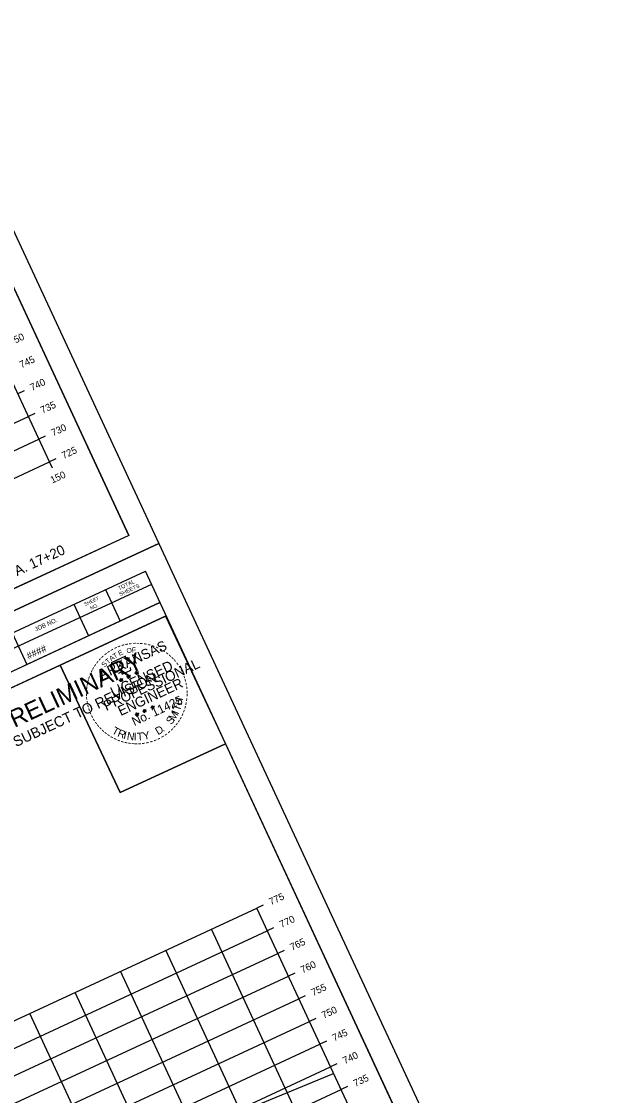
# Model space of a CAD drawing. Extents: x 1354696 to 1366163, y 660729 to 670380.
# Drawn here: x 1358367.5 to 1358484.8, y 665766.1 to 665980.8 of the extents above; entities that cross this region are included whole.
import ezdxf

# ---------------------------------------------------------------- set-up
doc = ezdxf.new("R2010")
doc.units = 0
for name, color, linetype in [('R_Axis', 7, 'Continuous'), ('R_Axis Annot', 7, 'Continuous'), ('R_Border', 7, 'Continuous'), ('R_Border PE', 7, 'Continuous'), ('R_Border Prem', 7, 'Continuous'), ('R_Draft', 7, 'Continuous'), ('R_Exist Surface', 7, 'Continuous'), ('R_Grid', 7, 'Continuous'), ('R_No Plot', 7, 'Continuous')]:
    doc.layers.add(name, color=color, linetype=linetype)

msp = doc.modelspace()

# ---------------------------------------------------------------- linework, layer by layer
at = {"layer": 'R_Axis'}
for p, q in [((1358373.11, 665892.75), (1358352.05, 665938.1)), ((1358368.06, 665906.95), (1358366.79, 665906.36)), ((1358370.17, 665902.41), (1358368.9, 665901.82)), ((1358372.27, 665897.88), (1358371, 665897.29)), ((1358101, 665766.42), (1358373.11, 665892.75)), ((1358374.38, 665893.34), (1358373.11, 665892.75)), ((1358373.7, 665891.48), (1358373.11, 665892.75)), ((1358415.79, 665804.15), (1358414.52, 665803.56)), ((1358435.57, 665758.21), (1358414.52, 665803.56)), ((1358417.89, 665799.61), (1358416.62, 665799.02)), ((1358420, 665795.08), (1358418.73, 665794.49)), ((1358422.1, 665790.54), (1358420.83, 665789.95)), ((1358424.21, 665786.01), (1358422.94, 665785.42)), ((1358426.32, 665781.47), (1358425.05, 665780.88)), ((1358428.42, 665776.94), (1358427.15, 665776.35)), ((1358430.53, 665772.4), (1358429.26, 665771.81)), ((1358432.63, 665767.87), (1358431.36, 665767.28))]:
    msp.add_line(p, q, dxfattribs=at)
at = {"layer": 'R_Border'}
for p, q in [((1358388.95, 665878.06), (1358302.43, 666064.41)), ((1358388.95, 665878.06), (1358102.17, 665744.91)), ((1358105.49, 665737.77), (1358392.27, 665870.91)), ((1358478.79, 665684.56), (1358392.27, 665870.91)), ((1358393.5, 665868.26), (1358393.5, 665868.26)), ((1358393.5, 665868.25), (1358354.41, 665850.1)), ((1358384.28, 665867.21), (1358387.21, 665860.91)), ((1358395.19, 665864.62), (1358356.1, 665846.47)), ((1358358.78, 665847.71), (1358395.19, 665864.62)), ((1358377.99, 665864.28), (1358380.91, 665857.99)), ((1358396.43, 665861.95), (1358339.61, 665835.57)), ((1358365.67, 665858.57), (1358368.6, 665852.27))]:
    msp.add_line(p, q, dxfattribs=at)
at = {"layer": 'R_Border PE'}
for p, q in [((1358387.07, 665849.07), (1358387.32, 665849.13)), ((1358387.07, 665849.07), (1358387.43, 665849.11)), ((1358387.07, 665849.07), (1358387.33, 665849.06)), ((1358387.43, 665849.11), (1358387.28, 665849.44)), ((1358387.28, 665849.44), (1358387.43, 665849.24)), ((1358387.28, 665849.44), (1358387.35, 665849.2)), ((1358387.36, 665848.75), (1358387.43, 665849.11)), ((1358387.36, 665848.75), (1358387.46, 665849.04)), ((1358387.36, 665848.75), (1358387.37, 665849.03)), ((1358387.7, 665849.36), (1358387.43, 665849.11)), ((1358387.75, 665848.93), (1358387.43, 665849.11)), ((1358387.7, 665849.36), (1358387.46, 665849.19)), ((1358387.75, 665848.93), (1358387.46, 665849.04)), ((1358387.75, 665848.93), (1358387.5, 665849.14)), ((1358387.7, 665849.36), (1358387.56, 665849.18)), ((1358388.58, 665849.77), (1358388.83, 665849.84)), ((1358388.58, 665849.77), (1358388.95, 665849.82)), ((1358388.58, 665849.77), (1358388.85, 665849.76)), ((1358388.95, 665849.82), (1358388.79, 665850.15)), ((1358388.79, 665850.15), (1358388.94, 665849.94)), ((1358388.79, 665850.15), (1358388.86, 665849.9)), ((1358388.87, 665849.46), (1358388.95, 665849.82)), ((1358388.87, 665849.46), (1358388.98, 665849.74)), ((1358388.87, 665849.46), (1358388.89, 665849.73)), ((1358389.21, 665850.06), (1358388.95, 665849.82)), ((1358389.26, 665849.64), (1358388.95, 665849.82)), ((1358389.21, 665850.06), (1358388.97, 665849.9)), ((1358389.26, 665849.64), (1358388.98, 665849.74)), ((1358389.26, 665849.64), (1358389.02, 665849.84)), ((1358389.21, 665850.06), (1358389.07, 665849.88)), ((1358390.19, 665850.5), (1358390.44, 665850.57)), ((1358390.19, 665850.5), (1358390.55, 665850.55)), ((1358390.19, 665850.5), (1358390.45, 665850.49)), ((1358390.55, 665850.55), (1358390.4, 665850.88)), ((1358390.4, 665850.88), (1358390.55, 665850.67)), ((1358390.4, 665850.88), (1358390.47, 665850.63)), ((1358390.48, 665850.19), (1358390.55, 665850.55)), ((1358390.48, 665850.19), (1358390.58, 665850.47)), ((1358390.48, 665850.19), (1358390.49, 665850.46)), ((1358390.82, 665850.79), (1358390.55, 665850.55)), ((1358390.87, 665850.37), (1358390.55, 665850.55)), ((1358390.82, 665850.79), (1358390.58, 665850.63)), ((1358390.87, 665850.37), (1358390.58, 665850.47)), ((1358390.87, 665850.37), (1358390.62, 665850.57)), ((1358390.82, 665850.79), (1358390.68, 665850.62)), ((1358390.62, 665842.24), (1358390.46, 665842.57)), ((1358390.46, 665842.57), (1358390.61, 665842.37)), ((1358390.46, 665842.57), (1358390.53, 665842.33)), ((1358390.88, 665842.49), (1358390.62, 665842.24)), ((1358390.88, 665842.49), (1358390.65, 665842.32)), ((1358390.88, 665842.49), (1358390.74, 665842.31)), ((1358391.77, 665842.9), (1358392.01, 665842.96)), ((1358391.77, 665842.9), (1358392.13, 665842.94)), ((1358391.77, 665842.9), (1358392.03, 665842.89)), ((1358392.13, 665842.94), (1358391.98, 665843.28)), ((1358391.98, 665843.28), (1358392.13, 665843.07)), ((1358391.98, 665843.28), (1358392.04, 665843.03)), ((1358392.06, 665842.58), (1358392.13, 665842.94)), ((1358392.06, 665842.58), (1358392.16, 665842.87)), ((1358392.06, 665842.58), (1358392.07, 665842.86)), ((1358392.4, 665843.19), (1358392.13, 665842.94)), ((1358392.45, 665842.77), (1358392.13, 665842.94)), ((1358392.4, 665843.19), (1358392.16, 665843.03)), ((1358392.45, 665842.77), (1358392.16, 665842.87)), ((1358392.45, 665842.77), (1358392.2, 665842.97)), ((1358392.4, 665843.19), (1358392.26, 665843.01)), ((1358393.37, 665843.63), (1358393.62, 665843.7)), ((1358393.37, 665843.63), (1358393.74, 665843.68)), ((1358393.37, 665843.63), (1358393.64, 665843.62)), ((1358393.74, 665843.68), (1358393.58, 665844.01)), ((1358393.58, 665844.01), (1358393.73, 665843.8)), ((1358393.58, 665844.01), (1358393.65, 665843.77)), ((1358393.67, 665843.32), (1358393.74, 665843.68)), ((1358393.67, 665843.32), (1358393.77, 665843.61)), ((1358393.67, 665843.32), (1358393.68, 665843.59)), ((1358394, 665843.93), (1358393.74, 665843.68)), ((1358394.05, 665843.5), (1358393.74, 665843.68)), ((1358394, 665843.93), (1358393.77, 665843.76)), ((1358394.05, 665843.5), (1358393.77, 665843.6)), ((1358394.05, 665843.5), (1358393.81, 665843.71)), ((1358394, 665843.93), (1358393.86, 665843.75)), ((1358390.25, 665842.2), (1358390.5, 665842.26)), ((1358390.25, 665842.2), (1358390.62, 665842.24)), ((1358390.25, 665842.2), (1358390.52, 665842.18)), ((1358390.55, 665841.88), (1358390.62, 665842.24)), ((1358390.55, 665841.88), (1358390.65, 665842.17)), ((1358390.55, 665841.88), (1358390.56, 665842.16)), ((1358390.93, 665842.06), (1358390.62, 665842.24)), ((1358390.93, 665842.06), (1358390.65, 665842.17)), ((1358390.93, 665842.06), (1358390.69, 665842.27))]:
    msp.add_line(p, q, dxfattribs=at)
for points in [[(1358389.04, 665853.24), (1358389.05, 665853.56), (1358388.44, 665853.25), (1358388.3, 665853.91), (1358385.47, 665852.6)], [(1358385.47, 665852.6), (1358386.06, 665851.96)], [(1358386.94, 665850.61), (1358386.97, 665850.53), (1358387.49, 665850.75), (1358387.64, 665850.3), (1358389.34, 665851.09), (1358389.3, 665851.66)], [(1358387.28, 665849.44), (1358387.75, 665848.93), (1358387.07, 665849.07), (1358387.7, 665849.36), (1358387.36, 665848.75), (1358387.28, 665849.44)], [(1358388.79, 665850.15), (1358389.26, 665849.64), (1358388.58, 665849.77), (1358389.21, 665850.06), (1358388.87, 665849.46), (1358388.79, 665850.15)], [(1358390.4, 665850.88), (1358390.87, 665850.37), (1358390.19, 665850.5), (1358390.82, 665850.79), (1358390.48, 665850.19), (1358390.4, 665850.88)], [(1358390.46, 665842.57), (1358390.93, 665842.06), (1358390.25, 665842.2), (1358390.88, 665842.49), (1358390.55, 665841.88), (1358390.46, 665842.57)], [(1358391.98, 665843.28), (1358392.45, 665842.77), (1358391.77, 665842.9), (1358392.4, 665843.19), (1358392.06, 665842.58), (1358391.98, 665843.28)], [(1358393.58, 665844.01), (1358394.05, 665843.5), (1358393.37, 665843.63), (1358394, 665843.93), (1358393.67, 665843.32), (1358393.58, 665844.01)]]:
    msp.add_lwpolyline(points, dxfattribs=at)
for centre, radius in [((1358387.43, 665849.11), 0.172), ((1358387.43, 665849.11), 0.145), ((1358387.43, 665849.11), 0.116), ((1358387.43, 665849.11), 0.0991), ((1358387.43, 665849.11), 0.0747), ((1358387.43, 665849.11), 0.0495), ((1358387.43, 665849.11), 0.0296), ((1358388.94, 665849.81), 0.172), ((1358388.94, 665849.81), 0.145), ((1358388.94, 665849.81), 0.116), ((1358388.94, 665849.81), 0.0991), ((1358388.94, 665849.81), 0.0747), ((1358388.94, 665849.81), 0.0495), ((1358388.94, 665849.81), 0.0296), ((1358390.55, 665850.55), 0.172), ((1358390.55, 665850.55), 0.145), ((1358390.55, 665850.55), 0.116), ((1358390.55, 665850.55), 0.0991), ((1358390.55, 665850.55), 0.0747), ((1358390.55, 665850.55), 0.0495), ((1358390.55, 665850.55), 0.0296), ((1358392.13, 665842.94), 0.172), ((1358392.13, 665842.94), 0.145), ((1358392.13, 665842.94), 0.116), ((1358392.13, 665842.94), 0.0991), ((1358392.13, 665842.94), 0.0747), ((1358392.13, 665842.94), 0.0495), ((1358392.13, 665842.94), 0.0296), ((1358393.74, 665843.68), 0.172), ((1358393.74, 665843.68), 0.145), ((1358393.74, 665843.68), 0.116), ((1358393.74, 665843.68), 0.0991), ((1358393.74, 665843.68), 0.0747), ((1358393.74, 665843.68), 0.0495), ((1358393.74, 665843.68), 0.0296), ((1358390.62, 665842.24), 0.172), ((1358390.62, 665842.24), 0.145), ((1358390.62, 665842.24), 0.116), ((1358390.62, 665842.24), 0.0991), ((1358390.62, 665842.24), 0.0747), ((1358390.62, 665842.24), 0.0495), ((1358390.62, 665842.24), 0.0296)]:
    msp.add_circle(centre, radius, dxfattribs=at)
at = {"layer": 'R_Exist Surface'}
msp.add_lwpolyline([(1358397.76, 665757.21), (1358429.86, 665770.52)], dxfattribs=at)
at = {"layer": 'R_Grid'}
for p, q in [((1358373.11, 665892.75), (1358352.05, 665938.1)), ((1358096.79, 665775.49), (1358368.9, 665901.82)), ((1358098.9, 665770.96), (1358371, 665897.29)), ((1358101, 665766.42), (1358373.11, 665892.75)), ((1358142.41, 665677.23), (1358414.52, 665803.56)), ((1358435.57, 665758.21), (1358414.52, 665803.56)), ((1358144.52, 665672.69), (1358416.62, 665799.02)), ((1358426.5, 665754), (1358405.45, 665799.35)), ((1358146.63, 665668.16), (1358418.73, 665794.49)), ((1358417.43, 665749.79), (1358396.38, 665795.14)), ((1358148.73, 665663.62), (1358420.83, 665789.95)), ((1358408.36, 665745.58), (1358387.31, 665790.93)), ((1358399.29, 665741.36), (1358378.24, 665786.72)), ((1358150.84, 665659.09), (1358422.94, 665785.42)), ((1358390.22, 665737.15), (1358369.17, 665782.5)), ((1358152.94, 665654.55), (1358425.05, 665780.88)), ((1358155.05, 665650.02), (1358427.15, 665776.35)), ((1358157.15, 665645.48), (1358429.26, 665771.81)), ((1358159.26, 665640.95), (1358431.36, 665767.28))]:
    msp.add_line(p, q, dxfattribs=at)
at = {"layer": 'R_No Plot'}
for p, q in [((1358092.6, 665736.08), (1358394.94, 665876.45)), ((1358092.6, 665736.08), (1358394.94, 665876.45)), ((1358384.15, 665831.49), (1358384.15, 665831.49))]:
    msp.add_line(p, q, dxfattribs=at)
for points in [[(1358002.76, 665929.58), (1358305.1, 666069.95), (1358394.94, 665876.45), (1358092.59, 665736.08)], [(1358227.82, 666029.77), (1358245.61, 666038.03), (1358249.77, 666029.07), (1358264.39, 666035.86), (1358285.43, 666045.63), (1358297.4, 666020.14), (1358318.45, 666029.91), (1358388.95, 665878.06), (1358102.17, 665744.91), (1358015.65, 665931.27)], [(1358092.59, 665736.08), (1358394.94, 665876.45), (1358484.77, 665682.95), (1358182.43, 665542.58)], [(1358375.27, 665852.13), (1358396.32, 665861.9), (1358408.28, 665836.41), (1358387.23, 665826.64)], [(1358317.66, 665836.27), (1358335.45, 665844.53), (1358339.61, 665835.57), (1358354.23, 665842.36), (1358375.27, 665852.13), (1358387.23, 665826.64), (1358408.28, 665836.41), (1358478.79, 665684.56), (1358192.01, 665551.41), (1358105.49, 665737.77)]]:
    msp.add_lwpolyline(points, close=True, dxfattribs=at)

# ---------------------------------------------------------------- texts
at = {"layer": 'R_Axis Annot'}
for s, p in [('750', (1358365.41, 665915.97)), ('745', (1358367.52, 665911.44)), ('740', (1358369.63, 665906.9)), ('735', (1358371.73, 665902.37)), ('730', (1358373.84, 665897.83)), ('725', (1358375.94, 665893.3)), ('150', (1358373.68, 665888.39)), ('775', (1358417.35, 665804.1)), ('770', (1358419.46, 665799.57)), ('765', (1358421.56, 665795.03)), ('760', (1358423.67, 665790.5)), ('755', (1358425.77, 665785.96)), ('750', (1358427.88, 665781.43)), ('745', (1358429.99, 665776.89)), ('740', (1358432.09, 665772.36)), ('735', (1358434.2, 665767.82))]:
    msp.add_text(s, height=1.4, rotation=24.9042, dxfattribs=at).set_placement(p)
at = {"layer": 'R_Border'}
for s, height, p in [('TOTAL', 0.782, (1358387.04, 665867.07)), ('SHEETS', 0.782, (1358387.28, 665865.88)), ('SHEET', 0.684, (1358380.22, 665863.91)), ('NO.', 0.684, (1358381.42, 665863.16)), ('JOB NO.', 0.879, (1358370.4, 665858.82)), ('####', 1.4, (1358368.92, 665853.23))]:
    msp.add_text(s, height=height, rotation=24.9042, dxfattribs=at).set_placement(p)
at = {"layer": 'R_Border PE'}
for s, height, rotation, p in [('ARKANSAS', 2, 24.9042, (1358383.58, 665849.2)), ('-', 1.6, 30.801, (1358385.6, 665854.47)), ('-', 1.6, 25.0904, (1358386.27, 665854.86)), ('-', 1.6, 22.6472, (1358386.93, 665855.15)), ('-', 1.6, 17.0659, (1358387.63, 665855.42)), ('-', 1.6, 12.1091, (1358388.33, 665855.61)), ('O', 1, 15.3557, (1358388.65, 665854.43)), ('-', 1.6, 7.2404, (1358388.97, 665855.74)), ('F', 1, 4.9748, (1358389.61, 665854.63)), ('-', 1.6, 2.7593, (1358389.73, 665855.85)), ('-', 1.6, 359.0253, (1358390.42, 665855.87)), ('-', 1.6, 354.5451, (1358391.06, 665855.86)), ('-', 1.6, 350.7668, (1358391.8, 665855.8)), ('-', 1.6, 345.4339, (1358392.53, 665855.67)), ('-', 1.6, 340.4828, (1358393.28, 665855.48)), ('-', 1.6, 334.7839, (1358394.03, 665855.22)), ('-', 1.6, 331.5563, (1358394.76, 665854.89)), ('-', 1.6, 49.2114, (1358383.4, 665852.58)), ('-', 1.6, 44.0802, (1358383.86, 665853.1)), ('-', 1.6, 38.5343, (1358384.44, 665853.63)), ('T', 1, 41.3078, (1358384.8, 665852.3)), ('-', 1.6, 35.1235, (1358384.99, 665854.06)), ('A', 1, 36.1173, (1358385.45, 665852.88)), ('T', 1, 30.9269, (1358386.15, 665853.38)), ('E', 1, 25.7365, (1358387.1, 665853.95)), ('-', 1.4, 328.5795, (1358395.44, 665854.58)), ('-', 1.6, 324.5725, (1358395.98, 665854.17)), ('-', 1.6, 319.567, (1358396.53, 665853.75)), ('-', 1.6, 315.477, (1358397.01, 665853.33)), ('-', 1.6, 310.0274, (1358397.47, 665852.91)), ('-', 1.6, 63.8548, (1358381.94, 665850.3)), ('-', 1.6, 61.1359, (1358382.21, 665850.84)), ('-', 1.6, 58.9677, (1358382.57, 665851.44)), ('-', 1.6, 53.696, (1358382.96, 665852.03)), ('S', 1, 46.4982, (1358384.11, 665851.62)), ('PROFESSIONAL', 2, 24.9042, (1358384.47, 665842.94)), ('LICENSED', 2, 24.9042, (1358385.87, 665845.69)), ('-', 1.6, 305.4535, (1358397.96, 665852.32)), ('-', 1.6, 301.5003, (1358398.43, 665851.69)), ('-', 1.6, 299.2343, (1358398.79, 665851.06)), ('-', 1.6, 75.5183, (1358381.36, 665848.51)), ('-', 1.6, 73.3272, (1358381.52, 665849.12)), ('-', 1.6, 67.8664, (1358381.73, 665849.74)), ('ENGINEER', 2, 24.9042, (1358387.35, 665841.93)), ('DWB', 0.01, 24.9042, (1358387.42, 665849.1)), ('DWB', 0.01, 24.9042, (1358388.94, 665849.81)), ('DWB', 0.01, 24.9042, (1358390.54, 665850.54)), ('-', 1.6, 294.8448, (1358399.09, 665850.5)), ('-', 1.6, 288.4214, (1358399.35, 665849.89)), ('-', 1.6, 285.8995, (1358399.56, 665849.27)), ('-', 1.6, 87.7755, (1358381.13, 665846.51)), ('-', 1.6, 82.9748, (1358381.15, 665847.2)), ('-', 1.6, 79.1366, (1358381.22, 665847.82)), ('-', 1.6, 280.6668, (1358399.75, 665848.6)), ('-', 1.6, 277.7723, (1358399.89, 665847.88)), ('-', 1.6, 272.7928, (1358399.97, 665847.17)), ('-', 1.6, 92.6784, (1358381.15, 665845.85)), ('-', 1.6, 97.2986, (1358381.21, 665845.19)), ('-', 1.6, 100.3651, (1358381.34, 665844.46)), ('No. 11425', 1.757, 24.9042, (1358390.07, 665839.94)), ('H', 1.54, 79.513, (1358399.57, 665844.05)), ('-', 1.6, 258.7494, (1358399.86, 665844.88)), ('-', 1.6, 263.9754, (1358399.95, 665845.64)), ('-', 1.6, 269.5239, (1358399.99, 665846.49)), ('-', 1.6, 106.1054, (1358381.52, 665843.75)), ('-', 1.6, 110.0905, (1358381.74, 665843.1)), ('-', 1.6, 113.9664, (1358382.01, 665842.45)), ('DWB', 0.01, 24.9042, (1358392.12, 665842.94)), ('DWB', 0.01, 24.9042, (1358393.73, 665843.67)), ('M', 1.54, 57.5605, (1358398.04, 665840.84)), ('I', 1.54, 67.0178, (1358398.85, 665842.15)), ('T', 1.54, 71.5486, (1358399.16, 665842.82)), ('-', 1.6, 245.9893, (1358399.26, 665842.79)), ('-', 1.6, 250.6695, (1358399.51, 665843.47)), ('-', 1.6, 256.1579, (1358399.71, 665844.19)), ('-', 1.6, 119.1, (1358382.35, 665841.81)), ('-', 1.6, 123.8521, (1358382.69, 665841.23)), ('-', 1.6, 126.6191, (1358383.13, 665840.62)), ('DWB', 0.01, 24.9042, (1358390.61, 665842.23)), ('S', 1.54, 51.8354, (1358397.45, 665840.12)), ('-', 1.6, 232.261, (1358398.27, 665841.01)), ('-', 1.6, 237.1533, (1358398.64, 665841.56)), ('-', 1.6, 240.6405, (1358398.96, 665842.13)), ('-', 1.6, 130.362, (1358383.52, 665840.15)), ('-', 1.6, 133.9916, (1358383.98, 665839.67)), ('-', 1.6, 138.9685, (1358384.47, 665839.24)), ('-', 1.6, 140.633, (1358385, 665838.8)), ('-', 1.6, 145.3513, (1358385.57, 665838.42)), ('T', 1.54, 330.9447, (1358385.44, 665838.56)), ('R', 1.54, 338.9091, (1358386.58, 665837.93)), ('I', 1.54, 346.8735, (1358387.79, 665837.46)), ('N', 1.54, 351.4044, (1358388.5, 665837.28)), ('I', 1.54, 0.2645, (1358389.93, 665837.07)), ('T', 1.54, 4.7953, (1358390.66, 665837.05)), ('Y', 1.54, 12.7597, (1358391.96, 665837.16)), ('D', 1.54, 31.3011, (1358394.81, 665838.09)), ('.', 1.54, 38.6683, (1358395.84, 665838.71)), ('-', 1.6, 216.1899, (1358396.31, 665838.95)), ('-', 1.6, 220.3785, (1358396.88, 665839.44)), ('-', 1.6, 225.6226, (1358397.4, 665839.95)), ('-', 1.6, 229.1558, (1358397.84, 665840.46)), ('-', 1.6, 150.7976, (1358386.17, 665838.08)), ('-', 1.6, 155.6223, (1358386.83, 665837.78)), ('-', 1.6, 159.128, (1358387.52, 665837.5)), ('-', 1.6, 163.838, (1358388.2, 665837.3)), ('-', 1.6, 169.5505, (1358388.87, 665837.17)), ('-', 1.6, 172.9939, (1358389.54, 665837.07)), ('-', 1.6, 176.4746, (1358390.2, 665837.02)), ('-', 1.6, 179.5044, (1358390.78, 665837.01)), ('-', 1.6, 183.4654, (1358391.45, 665837.04)), ('-', 1.6, 187.7024, (1358392.16, 665837.14)), ('-', 1.6, 192.4597, (1358392.88, 665837.29)), ('-', 1.6, 198.0196, (1358393.63, 665837.52)), ('-', 1.6, 201.4224, (1358394.33, 665837.79)), ('-', 1.6, 206.4959, (1358394.99, 665838.12)), ('-', 1.6, 210.7208, (1358395.7, 665838.53))]:
    msp.add_text(s, height=height, rotation=rotation, dxfattribs=at).set_placement(p)
at = {"layer": 'R_Border Prem'}
for s, height, p in [('PRELIMINARY', 3.5, (1358363.28, 665838.25)), ('SUBJECT TO REVISION', 2.0751, (1358366.44, 665835.72))]:
    msp.add_text(s, height=height, rotation=24.9042, dxfattribs=at).set_placement(p)
at = {"layer": 'R_Draft'}
msp.add_text('CROSS SECTION STA. 17+10 TO STA. 17+20', height=2, rotation=24.9042, dxfattribs=at).set_placement((1358325.21, 665850.67))

doc.saveas('drawing.dxf')
